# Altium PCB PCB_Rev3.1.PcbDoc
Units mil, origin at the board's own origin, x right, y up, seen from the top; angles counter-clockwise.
Board outline 1750.01 x 1055 mil, 4 copper layers (Top Layer, Layer 1 (GND), Layer 2 (PWR), Bottom Layer), stack 61.456 mil thick; 65 components, 52 nets, 278 pads, 123 vias.
Unrouted connection lines stored in the file: 3.
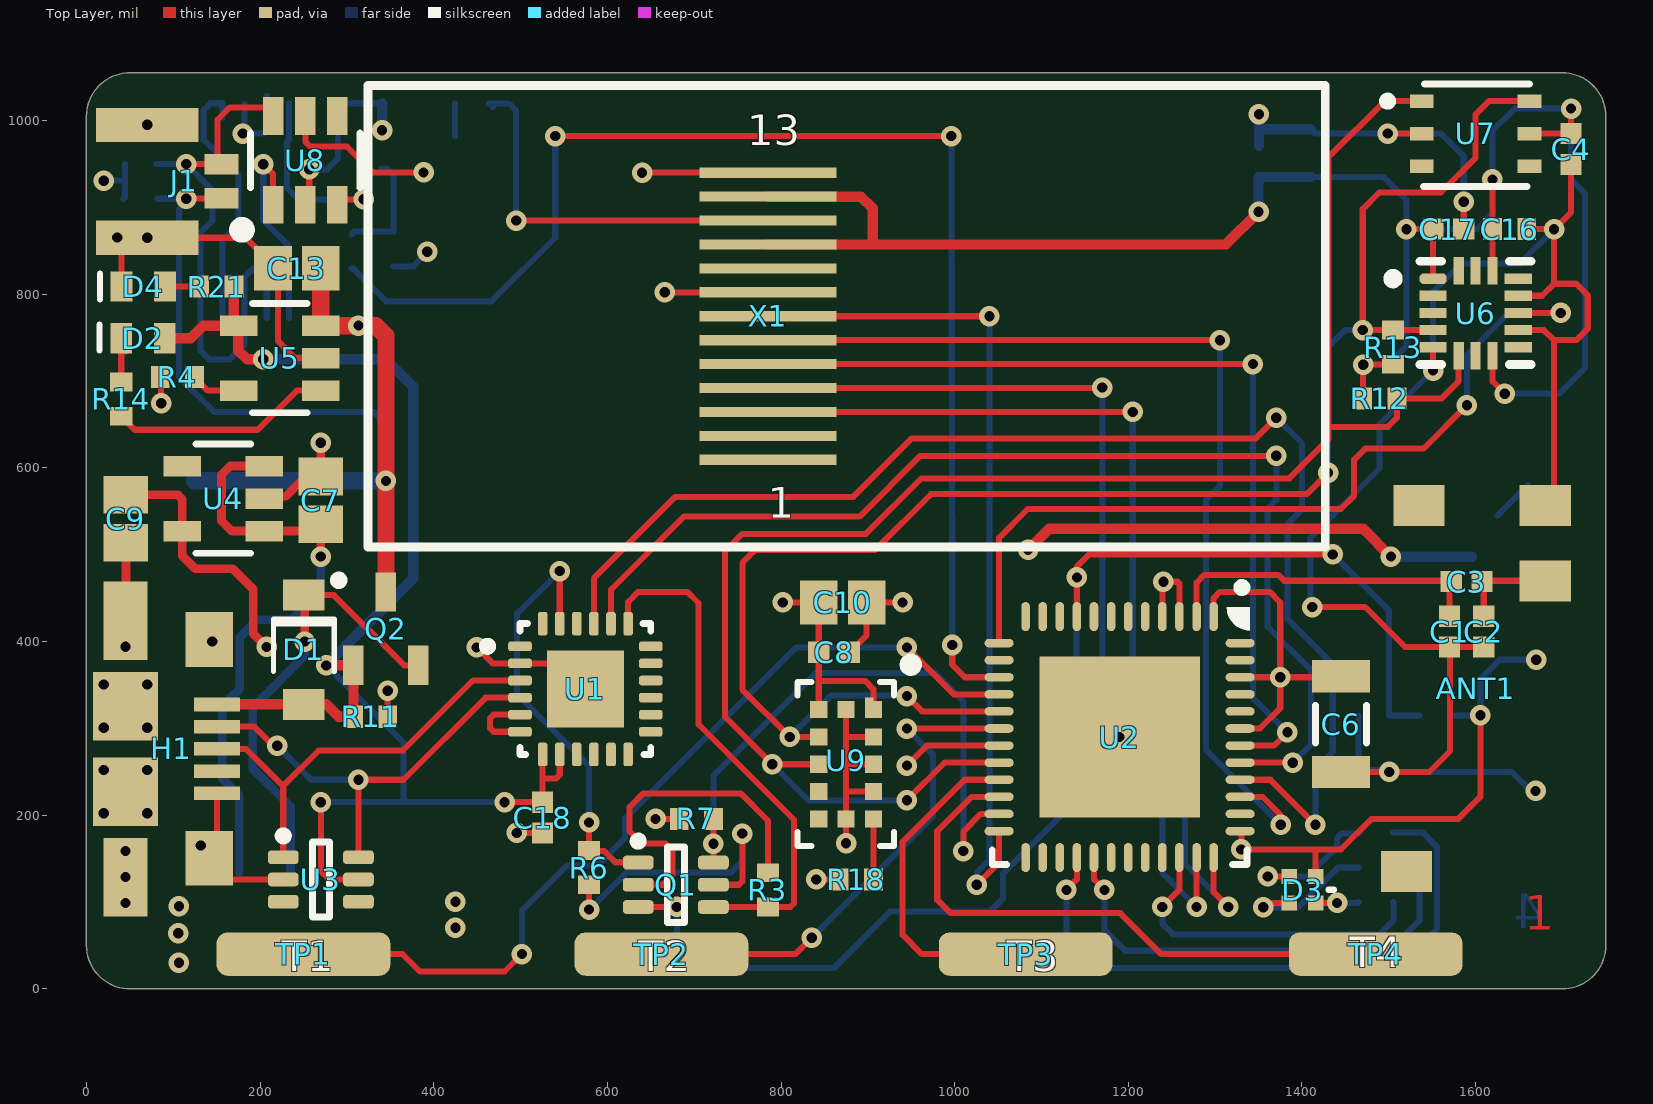
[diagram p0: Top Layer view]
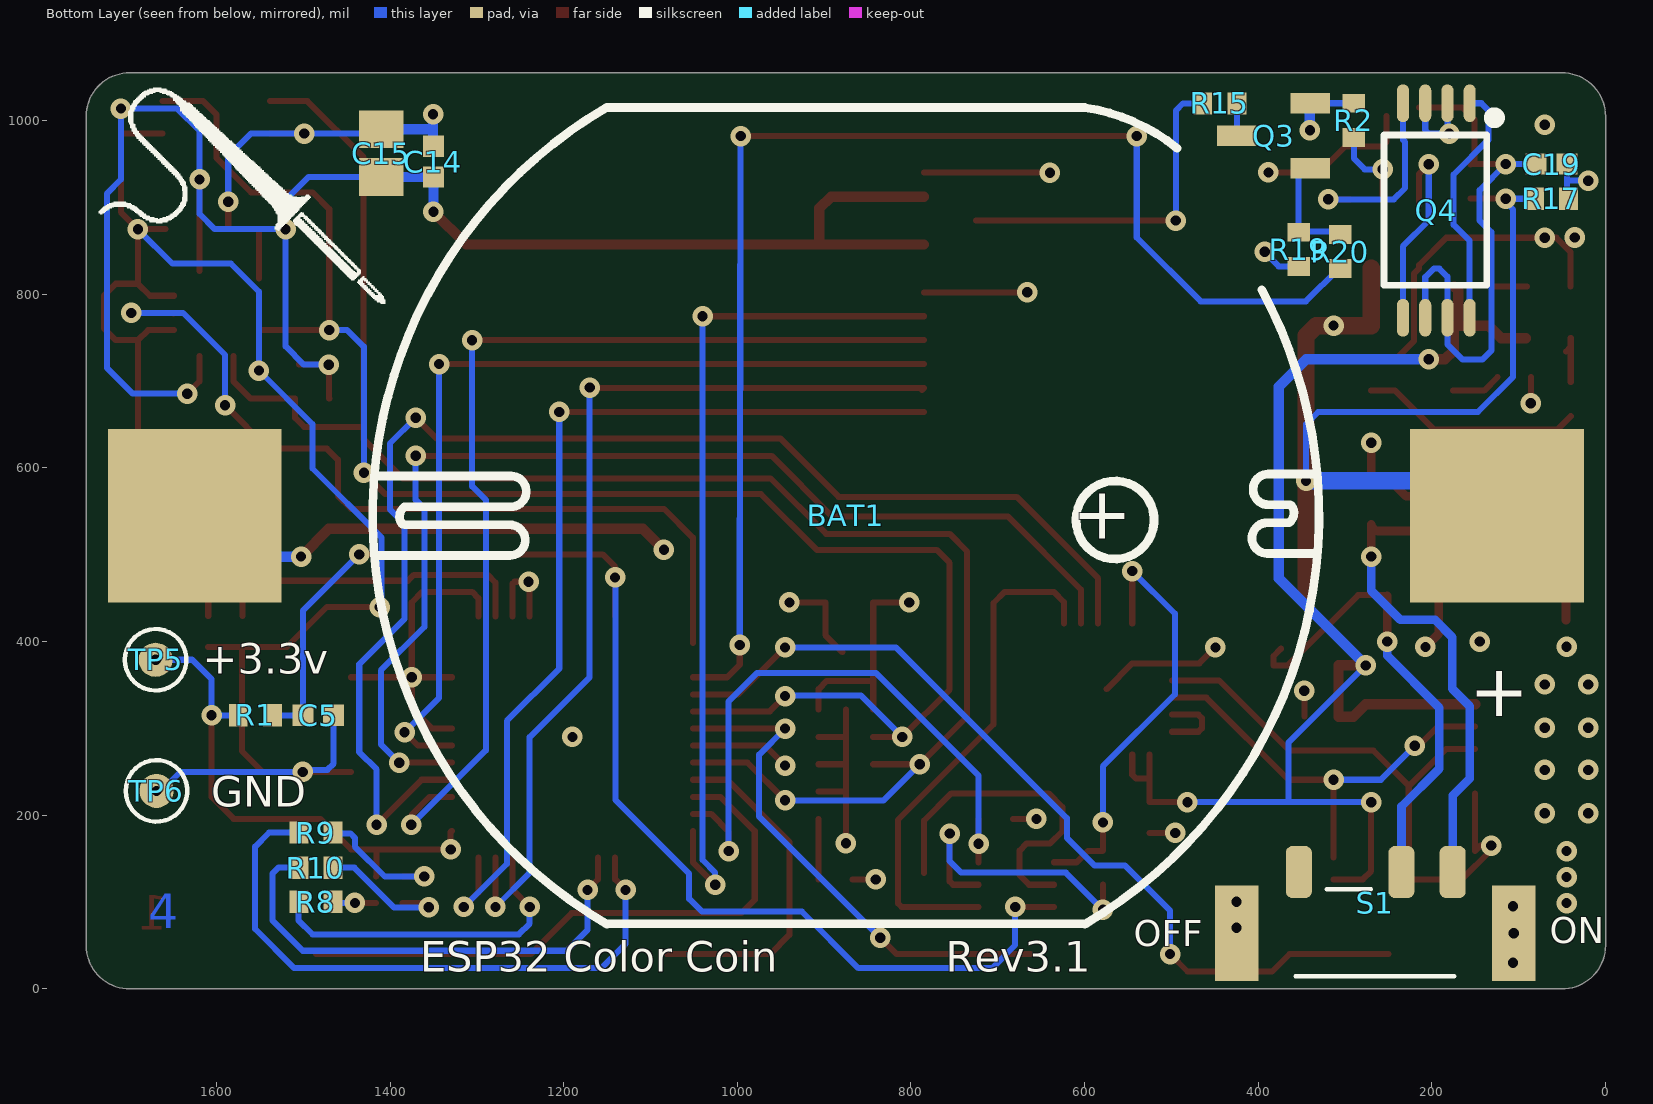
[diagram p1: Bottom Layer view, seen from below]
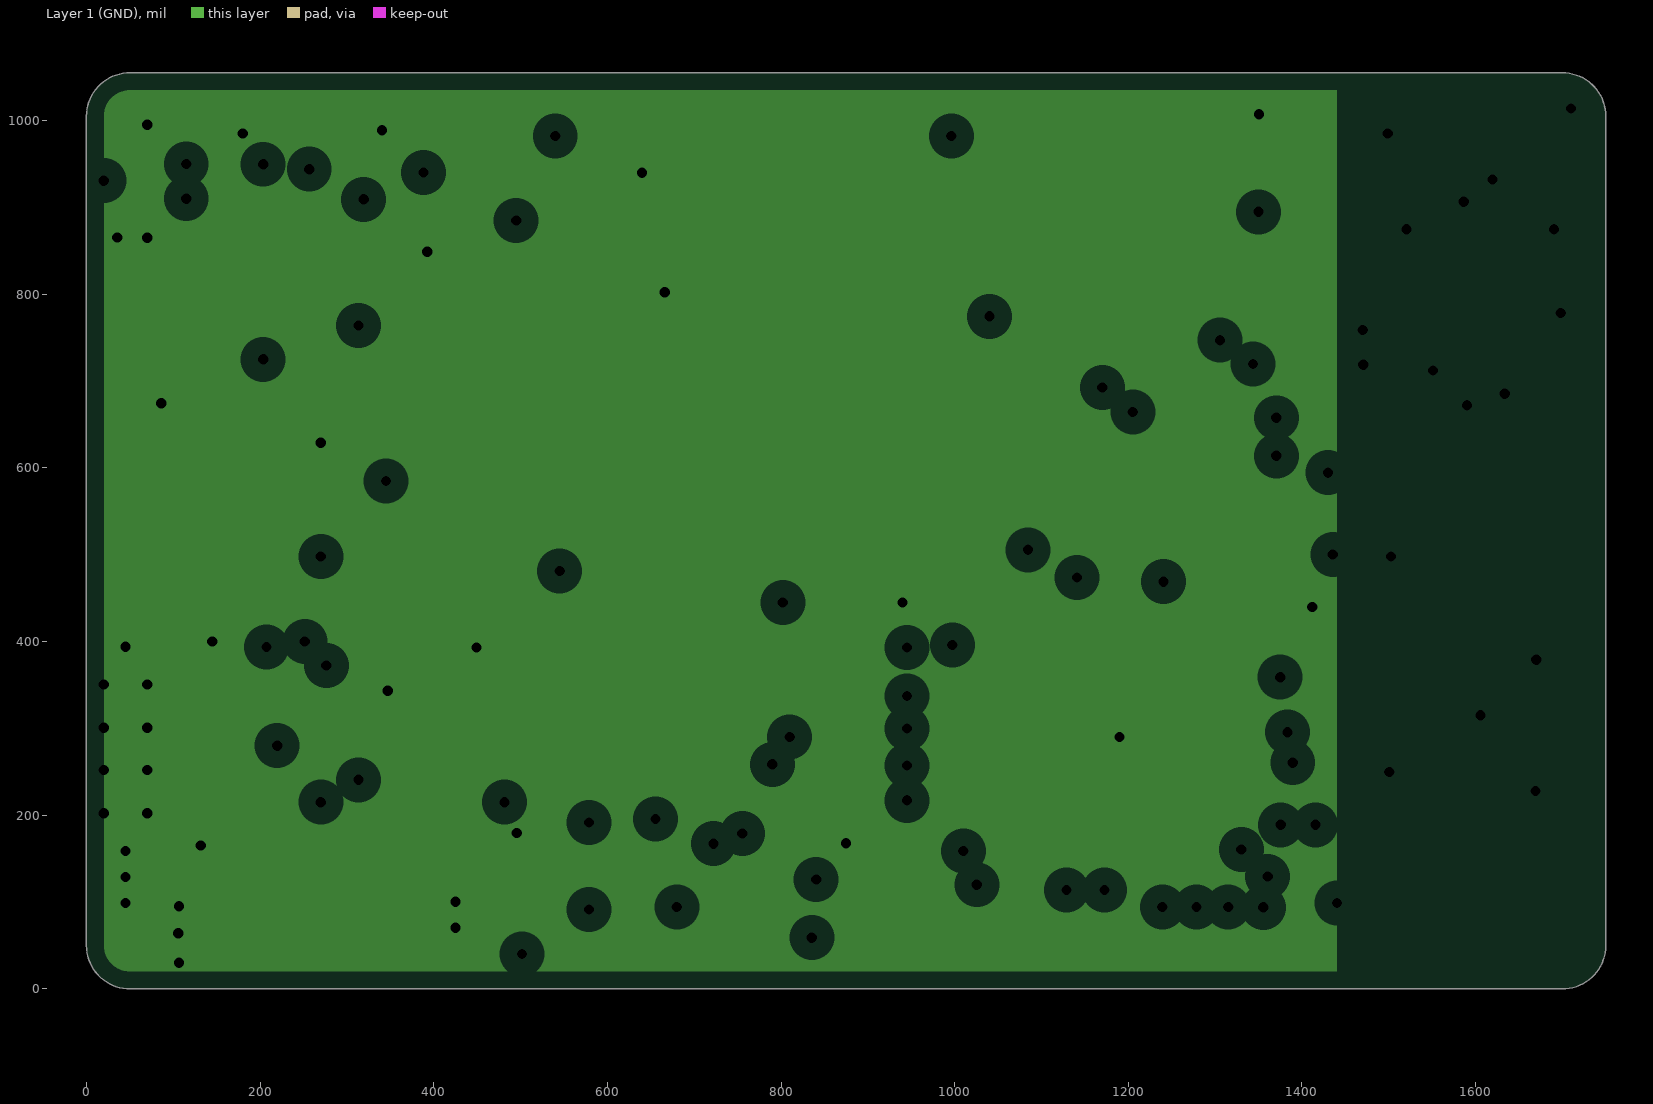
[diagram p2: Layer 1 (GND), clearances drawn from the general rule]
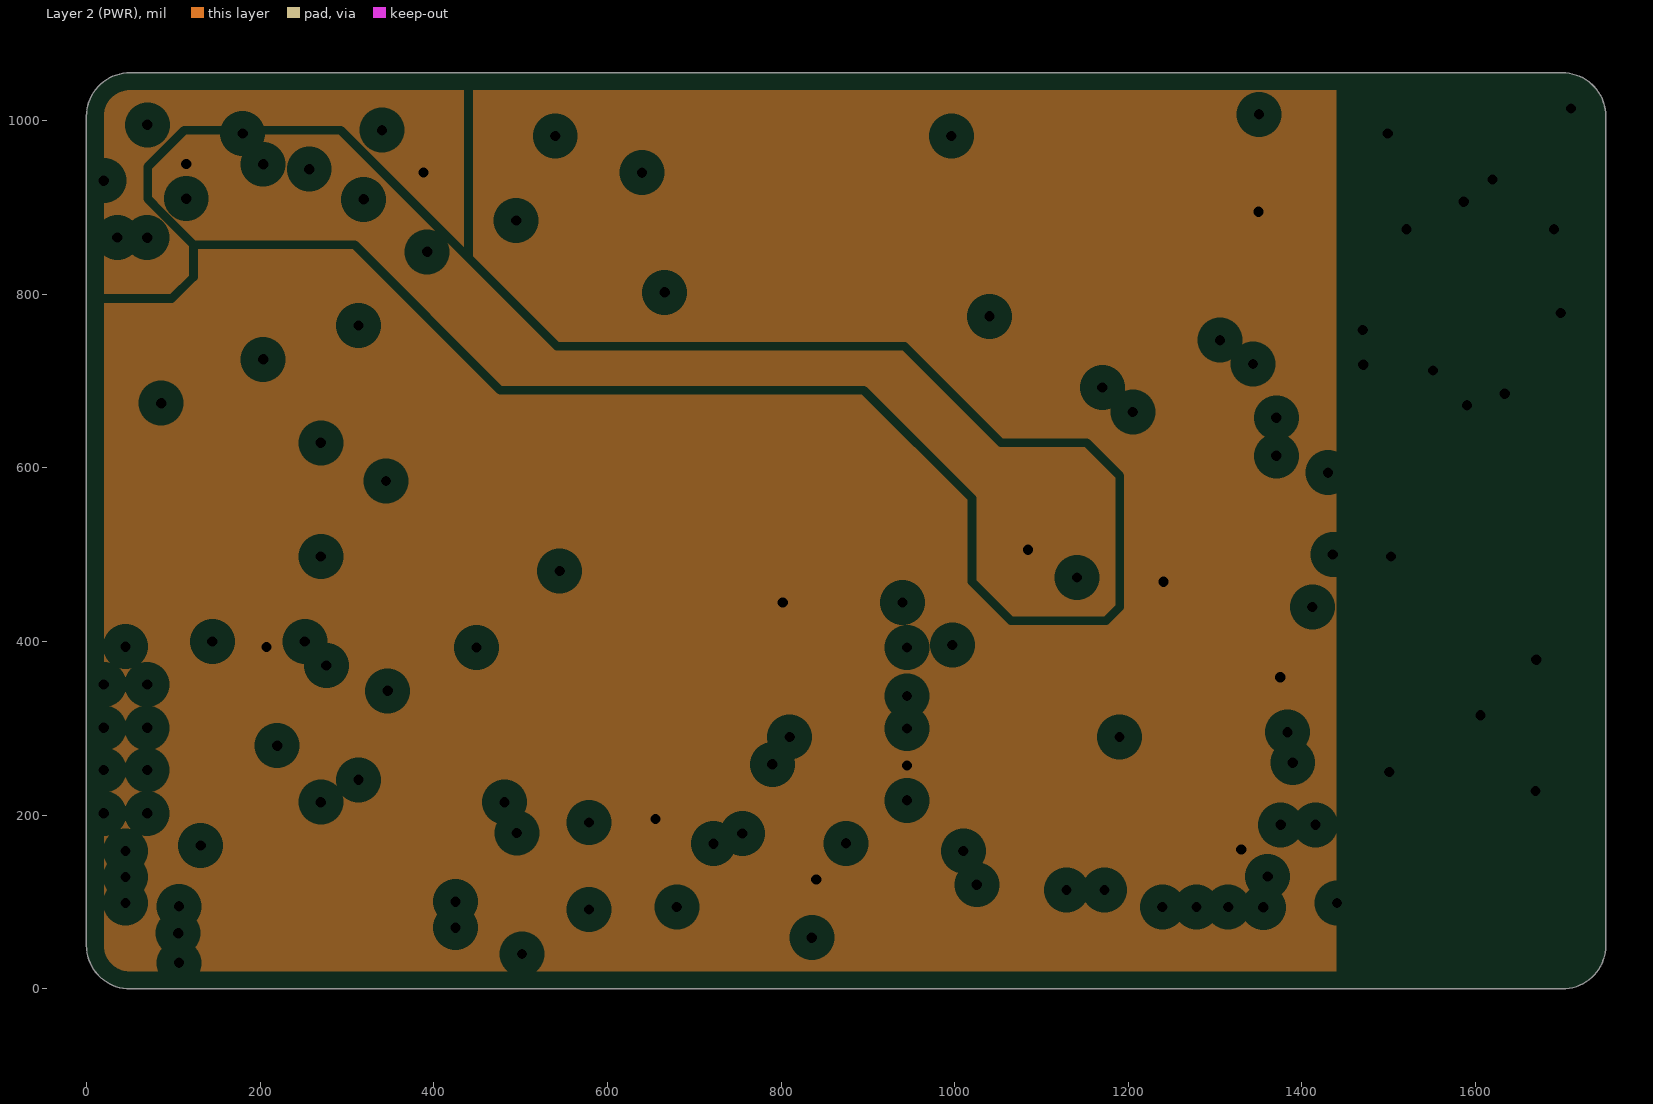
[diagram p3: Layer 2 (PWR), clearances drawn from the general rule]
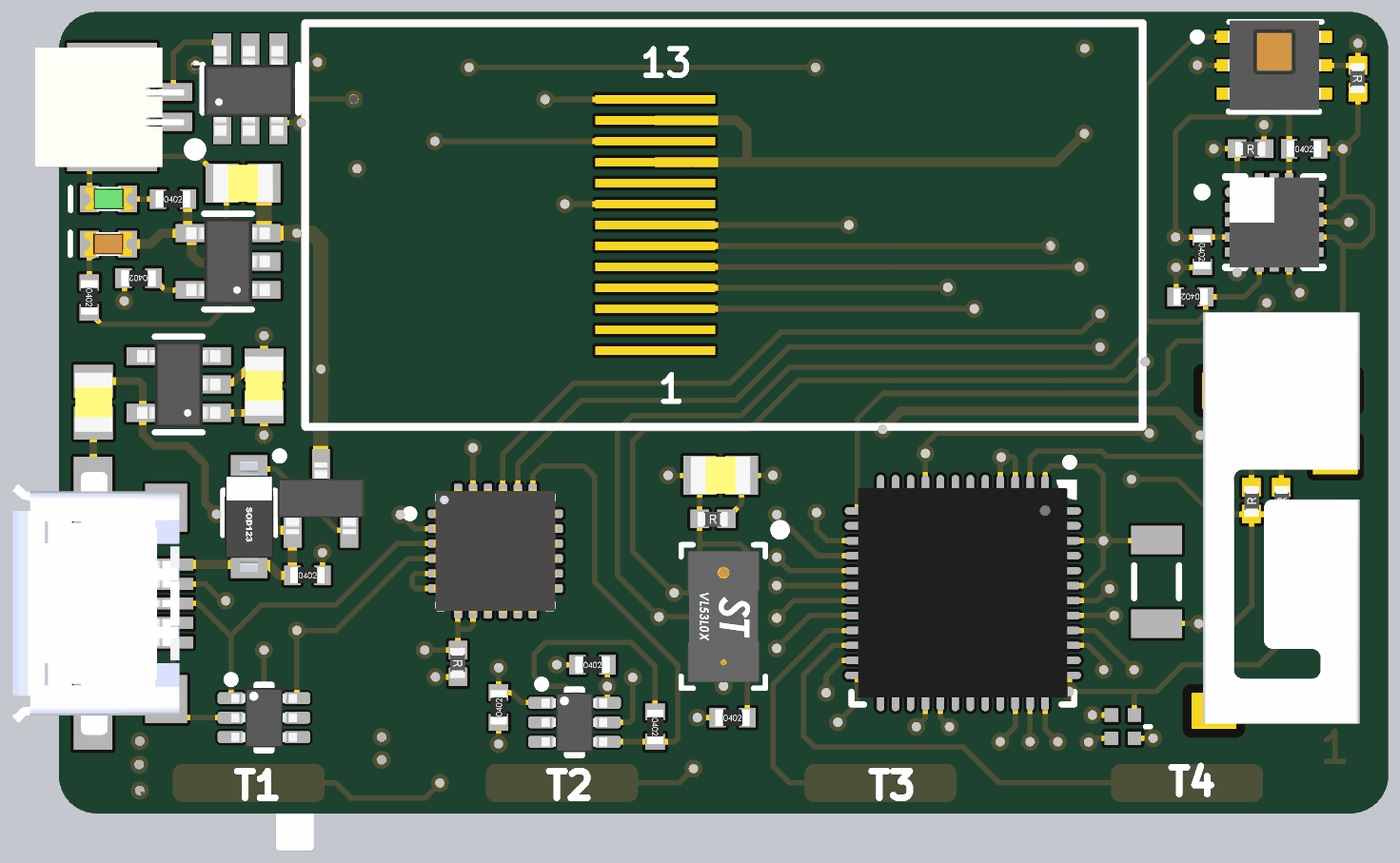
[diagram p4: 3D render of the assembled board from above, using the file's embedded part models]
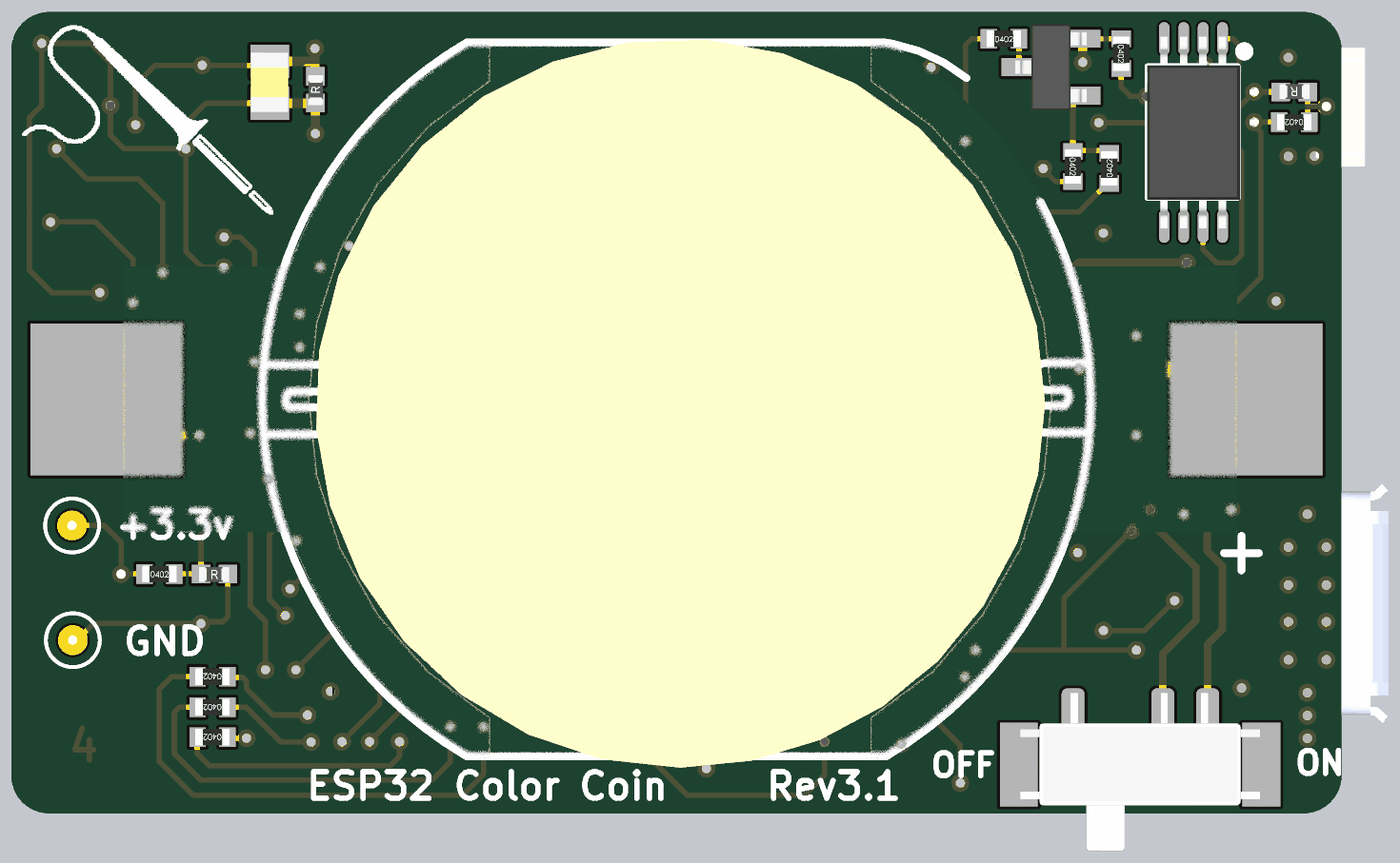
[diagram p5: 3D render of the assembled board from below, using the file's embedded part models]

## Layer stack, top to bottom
Top Solder: solder mask 0.4, Solder Resist, Dk 3.5
Top Layer: signal copper 1.4
Dielectric 2: prepreg 2.8, PP-006, Dk 4.1
Layer 1 (GND): plane copper 1.378, net GND
Dielectric 1: dielectric 50.3, FR-4, Dk 4.8
Layer 2 (PWR): plane copper 1.378, net (Multiple Nets)
Dielectric 3: prepreg 2.8, PP-006, Dk 4.1
Bottom Layer: signal copper 1.4
Bottom Solder: solder mask 0.4, Solder Resist, Dk 3.5

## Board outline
50.49,0 cw(c49.99,50) -0.01,50 -0.01,1005 cw(c49.99,1005) 50.49,1055 1699.48,1055 cw(c1699.98,1005.01) 1749.98,1005.01 1749.99,50 cw(c1699.99,50) 1699.49,0

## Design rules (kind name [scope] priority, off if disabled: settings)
Clearance Clearance_Q4 [InComponent('Q4')] p1: gap=9.2 ignorepadtopadclearanceinfootprint=FALSE
Clearance Clearance_U7 [All vs InComponent('U7')] p2: gap=7 ignorepadtopadclearanceinfootprint=FALSE
Clearance Clearance_H1 [All vs InComponent('H1')] p3: gap=9.5 ignorepadtopadclearanceinfootprint=FALSE
Clearance Clearance_U3 [All vs InComponent('U3')] p4: gap=9.5 ignorepadtopadclearanceinfootprint=FALSE
Clearance Clearance_Q1 [All vs InComponent('Q1')] p5: gap=9.5 ignorepadtopadclearanceinfootprint=FALSE
Clearance Clearance_X1 [All vs InComponent('X1')] p6: gap=8.5 ignorepadtopadclearanceinfootprint=FALSE
Clearance Clearance_U2 [All vs InComponent('U2')] p7: gap=9.5 ignorepadtopadclearanceinfootprint=FALSE
Clearance Clearance_U1 [All vs InComponent('U1')] p8: gap=7.8 ignorepadtopadclearanceinfootprint=FALSE
Clearance Clearance_U6 [All vs InComponent('U6')] p9: gap=7.5 ignorepadtopadclearanceinfootprint=FALSE
Clearance [All] p10: gap=10 ignorepadtopadclearanceinfootprint=FALSE except(0: Arc-Hole Track-Hole SMDPad-Hole THPad-Hole Via-Hole Fill-Hole Poly-Hole Region-Hole Text-Hole)
HoleSize [All] p1: absolutevalues=TRUE maxlimit=200 minlimit=1 maxpercent=80.000 minpercent=20.000
MinimumSolderMaskSliver MinimumSolderMaskSliver_U1 [All vs InComponent('U1')] p1: minsoldermaskwidth=0.5
MinimumSolderMaskSliver MinimumSolderMaskSliver_X1 [All vs InComponent('X1')] p2: minsoldermaskwidth=0.6
MinimumSolderMaskSliver [All] p3: minsoldermaskwidth=1
PlaneClearance [All] p1: clearance=20
PlaneConnect [All] p1: planeconnectstyle=Direct reliefexpansion=20 reliefentries=4 reliefconductorwidth=10 reliefairgap=10
PolygonConnect [All] p1: connectstyle=Relief reliefconductorwidth=10 reliefentries=4 polygonreliefangle="90 Angle" airgapwidth=10
RoutingVias [All] p1: holewidth=11.81 width=23.62 viastyle="Through Hole" minholewidth=11.81 minwidth=23.62 maxholewidth=11.81 maxwidth=23.62
SilkToSilkClearance [All] p1: silktosilkclearance=5
SilkToSolderMaskClearance [IsPad] p1: minsilkscreentomaskgap=5 clearancetoexposedcopper=TRUE
SolderMaskExpansion [All] p1: expansion=4 istentingtop=FALSE
Width [All] p1: maxlimit=40 minlimit=7 preferedwidth=7
24 further rules are at their usual default settings.

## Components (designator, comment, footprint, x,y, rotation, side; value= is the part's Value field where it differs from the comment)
ANT1 "RF ANT 2.4GHZ STAMPED MET SLD" PRO-OB-440 1680.36,556.61 r0 top locked
BAT1 "BATTERY-HOLDER (2450)" BU2450SM-JJ-GTR 874.99,545 r0 bottom locked value="Coin Cell Holder"
C1 "" CAPC1005X56N#1 1569.99,411.5 r90 top
C2 "" CAPC1005X56N#1 1609.36,411.5 r90 top
C3 "1.5pF" CAPC1005X56N#2 1589.71,469 r0 top
C4 "0.1uF" CAPC1005X56N#1 1709.99,967.28 r270 top
C5 "0.1uF" CAPC1005X56N#2 1482.71,315 r180 bottom
C6 "100uF" CAPC3216X160L 1444.99,304.88 r270 top
C7 "10uF" CAPC2012X140N 269.99,562.56 r90 top
C8 "0.1uF" CAPC1005X56N#2 861.21,387.76 r0 top
C9 "10uF" CAPC2012X140N 45.5,541.34 r270 top
C10 "10uF" CAPC2012X140N 871.05,445 r0 top
C13 "10uF" CAPC2012X140N 242.43,829.76 r180 top
C14 "0.1uF" CAPC1005X56N#2 1349.99,952.72 r90 bottom
C15 "10uF" CAPC2012X140N 1409.99,962.56 r90 bottom
C16 "0.1uF" RESC1005X40L 1639.13,875 r0 top
C17 "0.1uF" CAPC1005X56N#2 1568.66,875 r0 top
C18 "1uF" CAPC1005X56N#2 525.46,197.28 r270 top
C19 "0.1uF" CAPC1005X56N#2 62.27,950 r0 bottom
D1 "MBR0520" SOD123 250.5,390.56 r270 top
D2 "LED_0603" LED1608X55N-RED 65.13,749.53 r0 top value=Red
D3 "RGB" FC-B1010RGBT-HG 1400.76,114.15 r0 top value="RGB Led"
D4 "LED_0603" LED1608X55N-GREEN 65.5,808.9 r0 top locked value=Green
H1 "Micro USB" 1981584-1 97.64,276.38 r270 top
J1 "CON2" JST_Micro_2PIN 155.62,930.04 r270 top locked
Q1 "BC847S" SOT65P210X110-6N 678.81,118.9 r0 top value=2NPN
Q2 "FDN340P" SOT95P240X110-3N 344.99,414.84 r90 top value="Mosfet P-H"
Q3 "MMBT3904-TP" SOT95P240X110-3N 382.31,982.4 r0 bottom locked
Q4 "FS8205A" "TSOP65P490X110-8N WIDE" 194.95,896.48 r270 bottom locked
R1 "10K" RESC1005X40L 1555.11,315 r180 bottom
R2 "1K" RESC1005X40L 289.99,1000.32 r270 bottom
R3 "10K" RESC1005X40L 784.99,113.98 r270 top
R4 "43K" RESC1005X40L 104.81,704.53 r180 top
R6 "10K" RESC1005X40L 578.93,139.57 r90 top
R7 "10K" RESC1005X40L 702.43,195.67 r0 top
R8 "1K" RESC1005X40L 1485.31,100.21 r0 bottom
R9 "1K" RESC1005X40L 1485.31,180 r0 bottom
R10 "1K" RESC1005X40L 1485.31,139.58 r0 bottom
R11 "100K" RESC1005X40L 327.27,313.5 r0 top
R12 "2K" RESC1005X40L 1489.67,680 r180 top
R13 "2K" RESC1005X40L 1504.99,739.06 r270 top
R14 "2K" RESC1005X40L 40.13,679.21 r270 top
R15 "22R" RESC1005X40L 444.32,1019.8 r180 bottom
R17 "100R" RESC1005X40L 62.3,910 r0 bottom
R18 "10K" RESC1005X40L 886.8,125.98 r0 top
R19 "10K" RESC1005X40L 353.5,851.77 r270 bottom
R20 "1K" RESC1005X40L 305.5,849.21 r90 bottom
R21 "22K" RESC1005X40L 150.3,808.9 r0 top
S1 "SWITCH SLIDE" K3-1296S-E1 265.13,99.53 r180 bottom locked
TP1 "Test Point, 1mm Top Layer" TP100TL#1 302.05,-135 r90 top
TP2 "Test Point, 1mm Top Layer" TP100TL#2 662.27,40 r90 top
TP3 "Test Point, 1mm Top Layer" TP100TL#3 579.99,-145 r90 top
TP4 "Test Point, 1mm Top Layer" TP100TL#4 945.5,-121.1 r90 top
TP5 "Test Point, 1mm Top Layer" TP100TL#5 1669.99,379 r90 bottom
TP6 "Test Point, 1mm Top Layer" TP100TL#5 1668.99,228 r90 bottom
U1 "CP2104N" 24-QFN 574.67,345.28 r0 top
U2 "ESP32-PICO-D4" QFN48 1189.99,290 r270 top locked
U3 "PESD5V0L5UY" SOT65P210X110-6N 269.99,125 r0 top
U4 "HT7833" SOT95P280X144-5N 157.74,564.69 r180 top
U5 "SL4054ST25P" SOT95P280X144-5N 222.74,726.5 r180 top
U6 "LIS3DHTR" QFN3X3_16_1.2 1599.95,777.99 r0 top
U7 "HDC1080DMBT" HDC1080 1599.99,985 r0 top
U8 "DW01A" SOT95P280X130-6N 252.14,954.15 r90 top locked
U9 "VL53L0CXV0DH" VL53L0CXV0DH 874.99,263.09 r0 top locked value=VL53L0CXV0DH/1
X1 "TFT_0.96 inch" "TFT_GLASS 0.96 INCH" 966.09,774.65 r90 top locked

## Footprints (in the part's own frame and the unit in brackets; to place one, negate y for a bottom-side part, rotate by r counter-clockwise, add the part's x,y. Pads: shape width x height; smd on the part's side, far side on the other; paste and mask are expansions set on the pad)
24-QFN [mm] "24-QFN Exposed Pad (4x4)"
  rrect50% 0.69x0.28 smd: 1(-1.912,1.25) 2(-1.912,0.75) 3(-1.912,0.25) 4(-1.912,-0.25) 5(-1.912,-0.75) 6(-1.912,-1.25) 13(1.913,-1.25) 14(1.913,-0.75) 15(1.913,-0.25) 16(1.913,0.25) 17(1.913,0.75) 18(1.913,1.25)
  rrect50% 0.28x0.69 smd: 7(-1.25,-1.913) 8(-0.75,-1.913) 9(-0.25,-1.913) 10(0.25,-1.913) 11(0.75,-1.913) 12(1.25,-1.913) 19(1.25,1.913) 20(0.75,1.913) 21(0.25,1.913) 22(-0.25,1.913) 23(-0.75,1.913) 24(-1.25,1.913)
  rect 2.25x2.25 smd paste-1.3: 25(0,0)
  silkscreen extent -2.99,-1.91 1.91,1.91, body extent -2.05,-2.04 2.05,2.06, height 1.08
1981584-1 [mm] "CONN RCPT MICRO USB TYPE AB"
  rect 0.4x1.35 smd: 1(-1.3,1.338) 2(-0.65,1.338) 3(0,1.338) 4(0.65,1.338) 5(1.3,1.338)
  rect 2.3x1.3 smd: 6(-3.75,-1.337) 6(3.75,-1.337)
  rect 1.6x1.4 smd: 6(-3.2,1.113) 6(3.2,1.113)
  rect 2x1.9 smd: 6(-1.25,-1.337) 6(1.25,-1.337)
  body extent -4.4,-4.05 4.4,1.55, height 2.75
BU2450SM-JJ-GTR [mil] "HOLDER,BATT,COIN,24.5MM,SMT"
  rect 200x200 smd: 1(-750,0) 2(750,0)
  silkscreen extent -545,-470 545,470, body extent -842,-475 832,485, height 291
CAPC1005X56N#1 [mm] "Chip Capacitor, 2-Leads, Body 1.0x0.5mm, IPC Medium Density (0402 ceramic)"
  rect 0.62x0.62 smd paste-0.305: 1(-0.45,0) 2(0.45,0)
  body extent -0.55,-0.3 0.55,0.3, height 0.6
CAPC1005X56N#2 [mm] "Chip Capacitor, 2-Leads, Body 1.0x0.5mm, IPC Medium Density (0402 ceramic)"
  rect 0.62x0.62 smd: 1(-0.45,0) 2(0.45,0)
  body extent -0.55,-0.3 0.55,0.3, height 0.6
CAPC2012X140N [mm] "Chip Capacitor, 2-Leads, Body 2.0x1.3mm, IPC Medium Density (0805 ceramic)"
  rect 1.1x1.3 smd: 1(-0.7,0) 2(0.7,0)
  body extent -1,-0.62 1,0.63, height 1.24
CAPC3216X160L [mm] "Chip Capacitor, 2-Leads, Body 3.2x1.6mm, IPC Least Density(C1206)"
  rect 0.95x1.7 smd: 1(-1.4,0) 2(1.4,0)
  silkscreen extent -0.55,-0.75 0.55,0.75, body extent -1.7,-0.9 1.7,0.9, height 1.9
FC-B1010RGBT-HG [mm] "LED,RGB,SMD,RoHS"
  rect 0.45x0.45 smd: 1(0.387,0.388) 2(0.387,-0.387) 3(-0.387,-0.387) 4(-0.387,0.388)
  silkscreen extent 0.76,0 0.91,0, body extent -0.53,-0.55 0.53,0.58, height 0.9
HDC1080 [mm] "Temp/Humidity Sensor"
  rect 0.7x0.4 smd paste-0.381 mask+0.076: 1(-1.575,0.95) 2(-1.575,0) 3(-1.575,-0.95) 4(1.575,-0.95) 5(1.575,0) 6(1.575,0.95)
  silkscreen extent -2.7,-1.55 1.57,1.45, body extent -1.55,-1.5 1.55,1.5, height 0.85
JST_Micro_2PIN [mm]
  rect 0.6x1 smd: 1(0.5,0) 2(-0.5,0)
  rect 1x3 smd: ""(-1.65,-2.175) ""(1.65,-2.175)
  body extent -1.99,-4.74 2,0.24, height 2.9
K3-1296S-E1 [mil] "Toggle Switches SMD RoHS"
  rrect50% 30x60 smd: 1(89.06,35) 2(30,35) 3(-88.11,35)
  rect 50x110 smd: 4(-159.45,-35.43) 4(159.45,-35.43)
  silkscreen extent -92,-85 91,15, body extent -157,-149 158,59, height 60
LED1608X55N-GREEN [mil] "Chip LED GREEN 2-Leads, Body 1.6x0.8mm, IPC Medium Density (0603 med)"
  rect 25x35 smd: 1(-25,0) 2(25,0)
  body extent -31,-16 32,16, height 24
LED1608X55N-RED [mil] "Chip LED RED, 2-Leads, Body 1.6x0.8mm, IPC Medium Density (0603 med)"
  rect 25x35 smd: 1(-25,0) 2(25,0)
  body extent -31,-16 31,16, height 24
PRO-OB-440 [mm] "RF ANT 2.4GHZ STAMPED MET SLD"
  rect 1.5x1.2 smd paste-0.762 mask+0.2: 1(0,0) 2(0,-2.2)
  rect 1.5x1.2 smd paste-0.762 mask+0.3: 3(-3.7,0) 4(-4.064,-10.709)
  body extent -4.42,-11.14 0.81,2.61, height 3.56
QFN3X3_16_1.2 [mm] "QFN3X3_16_1.2"
  oct 0.8x0.3 smd: 1(-1.245,1.016)
  rect 0.8x0.3 smd: 2(-1.245,0.514) 3(-1.245,0.013) 4(-1.245,-0.489) 5(-1.245,-0.991) 9(1.245,-0.991) 10(1.245,-0.489) 11(1.245,0.013) 12(1.245,0.514) 13(1.245,1.016)
  rect 0.3x0.8 smd: 6(-0.495,-1.245) 7(0,-1.245) 8(0.495,-1.245) 14(0.495,1.245) 15(0,1.245) 16(-0.495,1.245)
  silkscreen extent -2.54,-1.5 1.63,1.52, body extent -1.51,-1.5 1.51,1.5, height 0.81
QFN48 [mm] "QFN, 48-Leads, Body 7x7mm, Pitch 0.5mm, IPC Medium Density"
  oval 0.85x0.25 smd: 1(-3.525,2.75) 2(-3.525,2.25) 3(-3.525,1.75) 4(-3.525,1.25) 5(-3.525,0.75) 6(-3.525,0.25) 7(-3.525,-0.25) 8(-3.525,-0.75) 9(-3.525,-1.25) 10(-3.525,-1.75) 11(-3.525,-2.25) 12(-3.525,-2.75) 25(3.525,-2.75) 26(3.525,-2.25) 27(3.525,-1.75) 28(3.525,-1.25) 29(3.525,-0.75) 30(3.525,-0.25) 31(3.525,0.25) 32(3.525,0.75) 33(3.525,1.25) 34(3.525,1.75) 35(3.525,2.25) 36(3.525,2.75)
  oval 0.25x0.85 smd: 13(-2.75,-3.525) 14(-2.25,-3.525) 15(-1.75,-3.525) 16(-1.25,-3.525) 17(-0.75,-3.525) 18(-0.25,-3.525) 19(0.25,-3.525) 20(0.75,-3.525) 21(1.25,-3.525) 22(1.75,-3.525) 23(2.25,-3.525) 24(2.75,-3.525) 37(2.75,3.525) 38(2.25,3.525) 39(1.75,3.525) 40(1.25,3.525) 41(0.75,3.525) 42(0.25,3.525) 43(-0.25,3.525) 44(-0.75,3.525) 45(-1.25,3.525) 46(-1.75,3.525) 47(-2.25,3.525) 48(-2.75,3.525)
  rect 4.7x4.7 smd paste-0.5: 49(0,0)
  silkscreen extent -4.5,-3.72 3.72,3.81, body extent -3.52,-3.51 3.5,3.51, height 0.78
RESC1005X40L [mm] "Chip Resistor, 2-Leads, Body 1.0x0.5mm, IPC Medium Density (0402)"
  rect 0.55x0.65 smd: 1(-0.5,0) 2(0.5,0)
  body extent -0.57,-0.27 0.58,0.28, height 0.41
SOD123 [mil] "Molded Diode, 2-Leads, Body 2.85x1.8mm, IPC Medium Density (SOD123)"
  rect 36x48 smd: 1(-63,0) 2(63,0)
  silkscreen extent -85,-35 25,45, body extent -73,-31 73,31, height 50
SOT65P210X110-6N [mm] "SC70, 6-Leads, Body 2.4x2.2mm (max), Pitch 0.65mm, IPC Medium Density"
  rrect50% 0.9x0.4 smd mask+0.076: 1(-1.1,0.675) 2(-1.1,0.025) 3(-1.1,-0.625) 4(1.1,-0.625) 5(1.1,0.025) 6(1.1,0.675)
  silkscreen extent -1.22,-1.07 0.25,1.42, body extent -1.1,-0.97 1.1,1.01, height 0.99
SOT95P240X110-3N [mm] "SOT23, 3-Leads, Body 3.0x2.5mm (max), Pitch 0.95mm, IPC Medium Density"
  rect 1.15x0.6 smd: 1(-1.075,0.95) 2(-1.075,-0.95) 3(1.075,0)
  body extent -1.2,-1.45 1.2,1.45, height 0.99
SOT95P280X130-6N [mm] "SOT23, 6-Leads, Body 3.0x3.0mm (max), Pitch 0.95mm, IPC Medium Density"
  rect 1.1x0.6 smd mask+0.051: 1(-1.3,0.94) 2(-1.3,0) 3(-1.3,-0.94) 4(1.3,-0.94) 5(1.3,0) 6(1.3,0.94)
  silkscreen extent -2.16,-1.6 0.8,1.98, body extent -1.57,-1.45 1.43,1.55, height 1.45
SOT95P280X144-5N [mm] "SOT23, 5-Leads, Body 3.1x3.0mm (max), Pitch 0.95mm, IPC Medium Density (RFMD SOT23-5)"
  rect 1.1x0.6 smd: 1(-1.2,0.95) 2(-1.2,0) 3(-1.2,-0.95) 4(1.2,-0.95) 5(1.2,0.95)
  silkscreen extent -0.8,-1.6 0.8,1.6, body extent -1.4,-1.45 1.4,1.45, height 1.45
"TFT_GLASS 0.96 INCH" [mm] "TFT_GLASS 0.96 INCH"
  rect 0.3x4 smd paste-0.305: 1(-4.2,4.6) 2(-3.5,4.6) 3(-2.8,4.6) 4(-2.1,4.6) 5(-1.4,4.6) 6(-0.7,4.6) 7(0,4.6) 8(0.7,4.6) 9(1.4,4.6) 10(2.1,4.6) 11(2.8,4.6) 12(3.5,4.6) 13(4.2,4.6)
  silkscreen extent -6.75,-11.7 6.75,16.3, body extent -6.75,-11.7 6.75,16.2, height 2
TP100TL#1 [mil] "Test Point"
  rrect50% 50x200 smd paste-80 mask-50: 1(175,52.06)
TP100TL#2 [mil] "Test Point"
  rrect50% 50x200 smd paste-80 mask+3: 1(0,0)
TP100TL#3 [mil] "Test Point"
  rrect50% 50x200 smd paste-80 mask-50: 1(185,-501.73)
TP100TL#4 [mil] "Test Point"
  rrect50% 50x200 smd paste-80 mask+3: 1(161.1,-539.49)
TP100TL#5 [mil] "Test Point"
  round 39.37 smd paste-19.68 mask+3: 1(0,0)
  silkscreen extent -35,-35 35,35
"TSOP65P490X110-8N WIDE" [mil] "TSOP, Wide, 8-Leads, Body 464x3.0mm (max), Pitch 0.65mm, IPC Medium Density"
  oval 43.5x14 smd mask+3: 1(-123.52,38.39) 2(-123.52,12.8) 3(-123.52,-12.8) 4(-123.52,-38.39) 5(123.52,-38.39) 6(123.52,-12.8) 7(123.52,12.8) 8(123.52,38.39)
  silkscreen extent -113,-60 86,73, body extent -126,-61 126,61, height 43
VL53L0CXV0DH [mm] "IC,LASER SENSOR,12pin"
  rect 0.25x0.25 smd: 1(0.675,1.713)
  rect 0.5x0.5 smd: 1(0.8,1.488) 2(0.8,0.687) 3(0.8,-0.112) 4(0.8,-0.913) 5(0.8,-1.712) 6(0,-1.712) 7(-0.8,-1.712) 8(-0.8,-0.912) 9(-0.8,-0.112) 10(-0.8,0.688) 11(-0.8,1.488) 12(0,1.488)
  silkscreen extent 1.69,2.6 2.09,3, body extent -1.2,-2.3 1.2,2.1, height 1

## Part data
ANT1: library part PRO-OB-440, Manufacturer="Proant AB"
BAT1: library part BU2450SM-JJ-GTR, "HOLDER,BATT,COIN,24.5MM,SMT", Manufacturer=MPD
C1 C2: library part CAP_0402, "DNP"
C3: library part CAP_0402, "CAP 1.5pF 0402", Manufacturer=Dafron
C4 C5 C8 C14 C16 C17 C19: library part CAP_0402, "CAP 0.1uF 0402", Manufacturer=CCTC, PartNumber=C344190
C6: library part CAP_1206, "CAP 100uF 6.3V 1206", Manufacturer="Taiyo Yuden", PartNumber=C87164
C7 C9 C10 C13 C15: library part CAP_0805, "CAP 10uF 0805", Manufacturer=Samsung, PartNumber=C307520
C18: library part CAP_0603, "CAP 1uF 16V 0402", Manufacturer=Walsin, PartNumber=C83063
D1: library part MBR0520-TP, "DIODE SCHOTTKY 20V 500MA SOD123", Manufacturer=CJ, PartNumber=C475717
D2: "LED RED CLEAR 0603 SMD", Manufacturer=FNO, PartNumber=C94869
D3: library part FC-B1010RGBT-HG, "LED,RGB LED,SMD,RoHS", Manufacturer=Foshan, PartNumber=C158099
D4: "LED Green 0603", Manufacturer=Lite-On, PartNumber=C125094
H1: library part 1981584-1, "CONN RCPT MICRO USB TYPE AB", Manufacturer="REG CON", PartNumber=C21377
J1: library part JST_Micro_CONN_2PIN, "JST MIcro CONN 2POS"
Q1: "TRANS 2NPN 44V 0.1A SC-70-6", Manufacturer=Changjiang
Q2: "MOSFET P-CH 20V 2A SOT-23", Manufacturer="On Semi", PartNumber=C75469
Q3: "TRANSISTOR NPN SOT23", Manufacturer="Micro Commercial", PartNumber=C668969
Q4: "MOSFET 2N-CH 20V 6A TSSOP-8L", Manufacturer=Fortune, PartNumber=C16052
R1 R3 R6 R7 R18 R19: library part RES_0402, "RES 10K 0402", Manufacturer=Guangdong, PartNumber=C258091
R2 R8 R9 R10 R20: library part RES_0402, "RES 1K 0402", Manufacturer=Yageo, PartNumber=C106235
R4: library part RES_0603, "RES 43K 0402", Manufacturer=Uniroyal, PartNumber=C8329
R11: library part RES_0603, "RES 100K 0402", Manufacturer="Uniroyal Elec", PartNumber=C25741
R12 R13: library part RES_0402, "RES 2K 0402", Manufacturer="LIZ Elec", PartNumber=C100291
R14: library part RES_0603, "RES 4.7K 0402", Manufacturer="LIZ Elec"
R15: library part RES_0402, "RES 22R 0402", Manufacturer=Uniroyal, PartNumber=C25092
R17: library part RES_0603, "RES 100R 0402", Manufacturer=Yageo, PartNumber=C106232
R21: library part RES_0603, "RES 22K 0402", Manufacturer="LIZ Elec"
S1: library part K3-1296S-E1, "SWITCH SLIDE SMD", Manufacturer="Korean Hroparts Elec", PartNumber=C128955
TP1 TP2 TP3 TP4 TP5 TP6: Manufacturer=N/A
U1: "IC BRIDGE USB TO UART 24QFN", Manufacturer="Silicon Labs", PartNumber=C47742
U2: "RF Transceiver ICs QFN-48_7x7x05P RoHS", Manufacturer=Espressif, PartNumber=C193707
U3: "TVS SOT-363 RoHS", Manufacturer=Yenji, PartNumber=C179747
U4: "IC LDO 3.3V 0.5A SOT23-5", Manufacturer=Holtek, PartNumber=C164106
U5: "Charger IC Lithium-Ion/Polymer SOT23-5", Manufacturer=Techfuse, PartNumber=C258510
U6: library part E-05-177, "IC ACCEL 2-16G I2C/SPI 16LGA", Manufacturer=STMicro, PartNumber=C15134
U7: "Humidity/Temperature Sensor", Manufacturer="Texas Instruments", PartNumber=C82227
U8: "IC LITHIUM BATT PROTECT SOT-23-6L", Manufacturer=PUOLOP
U9: "LASER SENSOR", Manufacturer="ST MICRO", PartNumber=C91199
X1: library part "TFT_GLASS 0.96 INCH COLOR", "0.96 INCH TFT GLASS COLOR", Manufacturer=BuyDisplay, PartNumber=ER-TFT0.96-1

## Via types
v1: diameter 23.62, hole 11.81, Top Layer to Bottom Layer, tented both sides, 123 vias

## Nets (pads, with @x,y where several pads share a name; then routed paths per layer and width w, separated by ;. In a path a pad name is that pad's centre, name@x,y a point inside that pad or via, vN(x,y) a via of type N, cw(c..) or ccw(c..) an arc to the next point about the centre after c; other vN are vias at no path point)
+3.3V: C4.1 C6.1 C8.1 C9.1 C10.1 C14.1 C15.1 C16.1 C17.1 D3.1 R1.1 R7.1 R12.2 R13.2 R18.1 TP5.1 U2.1 U2.3 U2.4 U2.19 U2.37 U2.43 U2.46 U4.5 U6.1 U6.8 U6.14 U7.5 U9.1 U9.11 X1.10 X1.12 | length 4122.7
  Top Layer w7: v1(655.5,195.67) R7.1 ; v1(802.11,445) C10.1 C8.1 843.49,354.71 ; v1(840.5,125.98) R18.1 ; U9.11 843.49,354.71 ; U9.1@906.48,321.65 906.48,345.28 897.05,354.71 843.49,354.71 ; v1(944.99,257.17) 967.98,280.16 U2.19 ; U2.4 1239.2,468.9 v1(1240.5,468.9) 1256.6,468.9 1258.89,466.61 U2.3 ; U2.1 1298.26,449.92 1305.5,457.17 1362.82,457.17 1374.99,445 v1(1374.99,358.9) ; U2.37 1328.99,181.73 1330.3,180.42 1330.13,180.25 v1(1330.13,160.53) 1415.5,160.53 ; U2.43 1351.44,299.84 1374.99,323.39 v1(1374.99,358.9) ; U2.46 v1(1374.99,358.9) ; D3.1 1415.5,129.92 1415.5,160.53 ; C6.1@1444.99,358.9 v1(1374.99,358.9) ; R12.2 1470.5,680.51 v1(1470.5,718.9) 1504.51,718.9 R13.2 ; v1(1520.36,875) C17.1 U6.1 ; v1(1605.5,315) 1605.5,221.1 1580.07,195.67 1480.13,195.67 1444.99,160.53 1415.5,160.53 ; U6.8 1619.45,699.55 v1(1633.47,685.53) ; U6.14 C16.1 v1(1619.45,932.17) ; U7.5 C4.1 v1(1709.99,1013.9)
  Top Layer w10: C9.1 105.5,568.9 110.5,563.9 U4.5 110.5,498.9 125.5,483.9 168.49,483.9 192.27,460.12 192.27,408.98 v1(207.47,393.78)
  Top Layer w12: X1.10 905.5,857.32 ; X1.12 891.96,912.44 905.5,898.9 905.5,857.32 ; v1(1349.99,895) 1312.31,857.32 905.5,857.32
  Bottom Layer w7: C15.1 1494,935 1520.36,908.64 v1(1520.36,875) ; v1(1470.5,718.9) 1499.4,718.9 1520.36,739.86 v1(1520.36,875) ; R1.1 v1(1605.5,315) 1605.5,356.63 1627.87,379 v1(1669.99,379) ; v1(1633.47,685.53) 1696.47,685.53 1726.19,715.25 1726.19,915.96 1709.99,932.17 v1(1709.99,1013.9) 1645.21,1013.9 1619.45,988.13 v1(1619.45,932.17) 1619.45,892.5 1601.95,875 v1(1520.36,875)
  Bottom Layer w12: v1(1349.99,895) C14.1 C15.1
BLUE: R9.2 U2.28 | length 713.5
  Top Layer w7: v1(1128.77,113.98) 1140.77,125.98 U2.28
  Bottom Layer w7: v1(1128.77,113.98) 1128.77,51.73 1156.6,23.9 1510.5,23.9 1555.5,68.9 1555.5,163.9 1539.4,180 R9.2
D+: H1.3 U1.3 U3.1 | length 498.5
  Top Layer w7: H1.3 183.49,276.38 226.01,233.86 ; U3.1 226.68,233.86 267.35,274.53 364.51,274.53 445.11,355.12 U1.3
D-: H1.2 U1.4 U3.6 | length 502.8
  Top Layer w7: H1.2 193.19,301.97 215.16,280 v1(219.66,280) ; U3.6 v1(313.29,240.79) 365.18,240.79 459.83,335.43 U1.4
  Bottom Layer w7: v1(219.66,280) 258.87,240.79 v1(313.29,240.79)
DC: U2.42 X1.5 | length 1059.7
  Top Layer w7: X1.5 v1(1343.5,719.53) ; U2.42 1367.78,280.16 v1(1383.22,295.59)
  Bottom Layer w7: v1(1343.5,719.53) 1343.5,335.31 v1(1383.22,295.59)
DTR: Q1.1 R6.2 U1.23 | length 499.6
  Top Layer w7: U1.23 v1(545.14,481.2) ; v1(578.93,191.69) R6.2 579.44,158.74 596.25,158.74 609.17,145.82 635.16,145.82 Q1.1
  Bottom Layer w7: v1(545.14,481.2) 495.93,431.99 495.93,339.21 578.93,256.22 v1(578.93,191.69)
EN: C5.1 Q1.3 R1.2 U2.9 | length 1518.5
  Top Layer w7: Q1.3 v1(679.99,94.29) ; U2.9 v1(1140.77,473.9) 1140.77,485.95 1155.22,500.39 v1(1435.5,500.39)
  Bottom Layer w7: v1(679.99,94.29) 679.99,50.51 706.6,23.9 860.5,23.9 925.5,88.9 1040.66,88.9 1055.5,103.74 1055.5,132.68 1140.5,217.68 1140.5,473.62 v1(1140.77,473.9) ; v1(1435.5,500.39) 1500.42,435.47 C5.1 R1.2
GND: ANT1.1 C1.1 C2.1 C4.2 C5.2 C6.2 C7.2 C8.2 C9.2 C10.2 C13.2 C14.2 C15.2 C16.2 C17.2 C18.2 D4.1 H1.5 H1.6 J1. Q3.2 Q4.2 Q4.3 R2.1 R4.2 R11.2 R19.2 S1.4 TP6.1 U1.2 U1.25 U2.49 U3.2 U4.2 U5.2 U6.5 U6.10 U6.12 U7.2 U9.2 U9.3 U9.4 U9.6 U9.12 X1.8 X1.13 | length 4242.5
  Top Layer w7: D4.1 40.5,848.89 56.68,865.08 v1(69.99,865.08) 183.49,865.08 214.87,833.7 C13.2 220.5,824.13 220.5,746.3 240.3,726.5 U5.2 ; H1.6@44.99,424.02 H1.6@45.5,424.53 ; v1(86.13,674.53) R4.2@86.13,704.53 ; H1.5 150.3,158.9 144.2,165 v1(131.56,165) 131.56,159.93 165.5,125.98 U3.2 ; U4.2 U4.2@207.47,567.17 ; C7.2@252.55,590.12 C7.2 ; R11.2 v1(346.96,343.19) ; v1(449.36,393.27) 467.83,374.8 U1.2 545.14,374.8 U1.25 ; v1(495.77,179.57) C18.2 ; v1(639.99,940) X1.13 ; v1(666.09,802.2) X1.8 ; v1(874.99,167.68) U9.6 874.99,227.17 ; U9.12 874.99,260.47 ; 876.8,290.16 U9.2 ; C8.2 898.61,407.44 C10.2 v1(939.99,445) ; U9.4 874.99,227.17 ; U9.3 876.8,258.66 874.99,260.47 ; v1(1412,439.76) 1472.66,439.76 1518.65,393.78 C1.1 ; C6.2 v1(1500.5,249.76) 1546.37,249.76 1570.5,273.9 1570.5,393.27 C1.1 ; v1(1498.77,985) U7.2 ; v1(1550.95,712.17) U6.5 ; C17.2 v1(1586.38,906.51) ; C2.1 C1.1 ; U6.10 1678.67,758.74 1690.32,747.09 ; U6.12 1676.49,798.24 1690.32,812.07 ; C16.2 v1(1690.32,875) ; ANT1.1 1690.32,566.58 1690.32,747.09 ; C4.2 1709.99,894.66 v1(1690.32,875) ; 874.99,227.17 874.99,260.47 ; 1690.32,747.09 1715.9,747.09 1729.19,760.37 1729.19,798.79 1715.9,812.07 1690.32,812.07 ; 1690.32,812.07 v1(1690.32,875)
  Top Layer w10: H1.6@45.5,424.53 C9.2 ; U4.2@207.47,567.17 229.59,567.17 C7.2@252.55,590.12 ; C7.2 v1(269.99,628.9)
  Bottom Layer w7: v1(180,985) 203.64,985 207.74,989.1 Q4.3@207.74,1028.48 ; v1@182.15,977.83 Q4.2@182.15,1019.11 ; R2.1 339.79,1020 Q3.2 Q3.2@340.5,1019.29 ; R19.2 376.5,832.08 392.5,848.08 v1(392.5,848.9) ; C14.2 C14.2@1350.5,970.94 ; 1350.5,989.05 1351.56,990.12 ; C15.2 1415.11,985 v1(1498.77,985) 1560.23,985 1586.38,958.85 v1(1586.38,906.51) ; v1(1412,439.76) 1410.01,441.75 1410.01,520.07 1489.28,599.33 1489.28,650.5 v1(1550.95,712.17) 1550.95,803 1583.19,835.25 1650.57,835.25 v1(1690.32,875) ; C5.2 1464.99,259.41 1472.23,252.17 1498.1,252.17 v1(1500.5,249.76) 1641.7,249.76 1663.47,228 v1(1668.99,228)
  Bottom Layer w12: v1(340.5,988.9) Q3.2@340.5,1019.29 ; C14.2@1350.5,970.94 1350.5,989.05 v1(1350.5,1007.17) ; 1351.56,990.12 C15.2
  other v1: 106.56,30 105.68,64.09 424.99,70.39 106.56,95 44.99,98.74 424.99,100.39 44.99,128.74 44.99,158.74 19.99,202.17 69.99,202.17 19.99,252.17 69.99,252.17 1189.99,290.16 19.99,300.59 69.99,300.59 19.99,350.59 69.99,350.59 44.99,394.02 144.99,400 35.62,865.35 70.14,995.15
GREEN: R10.2 U2.29 | length 562.8
  Top Layer w7: U2.29 1160.46,125.98 v1(1172.47,113.98)
  Bottom Layer w7: v1(1172.47,113.98) 1172.47,68.03 1196.6,43.9 1500.5,43.9 1535.5,78.9 1535.5,132.68 1528.59,139.58 R10.2
INT1: U2.13 U6.11 | length 983.4
  Top Layer w7: U2.13 1051.21,519.61 1084.5,552.9 1444.95,552.9 1460.13,568.08 1460.13,609.53 1472.77,622.17 1539.99,622.17 v1(1589.99,672.17) ; U6.11 1649.44,778 1649.93,778.49 v1(1698.19,778.49)
  Bottom Layer w7: v1(1589.99,672.17) 1589.99,730 1638.48,778.49 v1(1698.19,778.49)
IO0: Q1.6 R7.2 U2.23 | length 723.4
  Top Layer w7: Q1.6 v1(722.11,167.17) R7.2 ; v1(1009.99,158.74) 1009.99,181.18 1030.22,201.42 U2.23
  Bottom Layer w7: v1(722.11,167.17) 722.11,245.51 840.5,363.9 977.19,363.9 1009.99,331.1 v1(1009.99,158.74)
LCD_BL: R20.1 U2.15 | length 1522.1
  Top Layer w7: v1(539.99,982.17) v1(996.13,982.17) ; v1(997.27,396.02) 997.27,373.5 1011.88,358.9 U2.15
  Bottom Layer w7: R20.1 307.47,829.53 345.15,791.85 466.45,791.85 539.99,865.39 v1(539.99,982.17) ; v1(996.13,982.17) v1(997.27,396.02)
NetANT1_2: ANT1.2 C2.2 C3.2 | length 111.8
  Top Layer w7: C2.2 1609.36,470 ANT1.2
NetBAT1_2: BAT1.2 C19.2 J1.2 Q4.6 Q4.7 U8.6 | length 1236.7
  Top Layer w7: v1(114.99,950) 155.34,950 J1.2 151,954.34 151,1001 165.15,1015.15 U8.6@214.87,1015.15
  Top Layer w12: v1(1084.5,505.63) 1108.87,530 1470.4,530 v1(1502.5,497.9)
  Bottom Layer w7: C19.2 v1(114.99,950) 144.99,920 144.99,884.88 131.56,871.45 131.56,735 141.56,725 164.99,725 182.15,742.17 Q4.7 182.15,820.12 191.56,829.53 197.84,829.53 207.74,819.63 Q4.6 ; BAT1.2 BAT1.2@1660.5,580.51
  Bottom Layer w12: v1(1502.5,497.9) BAT1.2@1595.89,497.9
NetC1_2: C1.2 C3.1 U2.2 | length 377.8
  Top Layer w7: U2.2 1278.57,467.8 1287.63,476.85 1372.55,476.85 1379.4,470 1569.99,470 C1.2
NetC7_1: C7.1 S1.1 U4.1 U4.3 | length 708
  Top Layer w7: C7.1@262.27,527.28 C7.1
  Top Layer w10: U4.3 165.62,602.09 155.62,592.09 155.62,538.98 167.31,527.28 U4.1 C7.1@262.27,527.28 ; v1(269.99,497.9) C7.1
  Bottom Layer w10: S1.1 176.07,222.65 156.56,242.17 156.56,325.59 176.56,345.59 176.56,405 196.56,425 236.56,425 269.99,458.43 v1(269.99,497.9)
NetC19_1: C19.1 R17.1 U8.5 | length 245.9
  Top Layer w7: U8.5 252.14,975.71 257.7,970.15 299.9,970.15 329.74,940.32 v1(388.28,940.32)
  Bottom Layer w7: v1(19.99,930.8) 20.16,930.97 44.55,930.97 ; R17.1 44.55,911.94 44.55,930.97 ; C19.1 44.55,930.97
NetD1_1: D1.1 Q2.2 S1.2 | length 550.4
  Top Layer w7: D1.1@251.56,452.5 D1.1 285.05,453.56 366.09,372.52 Q2.2 382.39,383.35 Q2.2@374.08,391.66
  Top Layer w10: v1(251.56,400) D1.1@251.56,452.5
  Bottom Layer w10: S1.2 235.13,210 191.56,253.57 191.56,323.9 251.56,383.9 v1(251.56,400)
NetD2_1: D2.1 R14.1 | length 57.7
  Top Layer w7: R14.1 D2.1 ; D2.1@40.5,738.9 D2.1@45.5,733.9
NetD3_2: D3.2 R8.1 | length 50.2
  Top Layer w7: D3.2 v1(1440.5,98.9)
  Bottom Layer w7: v1(1440.5,98.9) 1464.31,98.9 R8.1
NetD3_3: D3.3 R10.1 | length 161.1
  Top Layer w7: v1(1355.5,93.9) 1360.5,98.9 D3.3
  Bottom Layer w7: v1(1355.5,93.9) 1395.5,93.9 1441.18,139.58 R10.1
NetD3_4: D3.4 R9.1 | length 156.9
  Top Layer w7: v1(1360.5,129.41) D3.4
  Bottom Layer w7: v1(1360.5,129.41) 1406.01,129.41 1440.5,163.9 1440.5,173.9 1445.5,178.9 1464.52,178.9 R9.1
NetD4_2: D4.2 R21.1 | length 40.1
  Top Layer w7: D4.2 R21.1
NetQ1_2: Q1.2 R3.1 | length 397.8
  Top Layer w7: Q1.2 663.88,119.88 674.99,130.98 674.99,159.25 667.07,167.17 640.07,167.17 625.5,181.73 625.5,209.24 641.46,225.2 753.46,225.2 784.99,193.67 R3.1
NetQ1_5: Q1.5 R6.1 | length 355.1
  Top Layer w7: v1(578.93,91.26) R6.1 ; Q1.5 751.48,119.88 755.5,123.9 v1(755.5,178.9) 758.77,178.9 v1@759.99,177.68
  Bottom Layer w7: v1(578.93,91.26) 621.56,133.9 742.23,133.9 755.5,147.17 v1(755.5,178.9)
NetQ3_1: Q3.1 R19.1 R20.2 | length 131.7
  Bottom Layer w7: R20.2 309.06,872.46 R19.1@353.5,872.46 ; Q3.1 345.19,945 353.5,936.69 R19.1@353.5,872.46 ; R19.1 R19.1@353.5,872.46
NetQ3_3: Q3.3 R15.2 | length 37.4
  Bottom Layer w7: Q3.3 R15.2
NetQ4_1: Q4.1 Q4.8 | length 304.2
  Bottom Layer w7: Q4.1@156,1020 143,1020 135,1012 135,977.89 174.99,937.9 174.99,880 156.6,861.61 Q4.8@156.6,772.95 ; Q4.1@156.56,1003.36 Q4.1
NetQ4_4: Q4.4 U8.3 | length 217.4
  Top Layer w7: U8.3@294.17,909.32 v1(319.28,909.32)
  Bottom Layer w7: Q4.4 233.33,977.83 230.99,975.49 230.99,922.34 244.01,909.32 v1(319.28,909.32)
NetQ4_5: Q4.5 U8.1 | length 240.6
  Top Layer w7: v1(203.64,949.72) 215.13,938.24 U8.1
  Bottom Layer w7: v1(203.64,949.72) 203.64,884.91 233.37,855.18 Q4.5
NetR2_2: R2.2 U8.2 | length 99.4
  Top Layer w7: U8.2@256.65,907.48 v1(256.65,944.05)
  Bottom Layer w7: v1@256.5,943.9 277.45,943.9 289.99,956.44 R2.2
NetR4_1: R4.1 U5.5 | length 57.4
  Top Layer w7: R4.1 139.93,689.09 U5.5
NetR14_2: R14.2 U5.1 | length 255.1
  Top Layer w7: R14.2 55.76,643.9 197.27,643.9 242.47,689.09 U5.1
NetR15_1: R15.1 X1.11 | length 396.7
  Top Layer w7: v1(494.99,884.88) X1.11@724.99,884.88
  Bottom Layer w7: R15.1@468.03,1015.77 R15.1 486.7,1019.8 494.99,1011.51 v1(494.99,884.88)
NetU1_5: U1.5 U1.6 | length 83.7
  Top Layer w7: U1.6 469.09,296.06 464.99,300.16 464.99,311.65 469.09,315.75 U1.5
RED: R8.2 U2.34 | length 385.7
  Top Layer w7: v1(1239.2,94.29) 1258.89,113.98 U2.34
  Bottom Layer w7: v1@1240.5,92.99 v1(1239.2,94.29) 1239.2,75.2 1251.72,62.68 1489.28,62.68 1505.5,78.9 1505.5,99.7 R8.2
RST: U2.39 X1.6 | length 1187.5
  Top Layer w7: X1.6 v1(1305.5,747.09) ; U2.39 1354.55,221.1 1375.5,200.16 v1(1375.5,188.9)
  Bottom Layer w7: v1(1305.5,747.09) 1305.5,578.9 1289.68,563.08 1289.68,274.72 v1(1375.5,188.9)
RTS: Q1.4 R3.2 U1.19 | length 602.3
  Top Layer w7: U1.19 623.88,445.55 635.5,457.17 692.19,457.17 704.99,444.37 704.99,304.67 814.99,194.67 814.99,98.39 810.89,94.29 R3.2 Q1.4
RXD: U1.21 U2.40 | length 1541.1
  Top Layer w7: U1.21 584.51,472.8 678.3,566.58 883.18,566.58 950.5,633.9 1346.64,633.9 v1(1370.5,657.76) ; U2.40 1363.61,240.79 v1(1415.5,188.9)
  Bottom Layer w7: v1(1370.5,657.76) 1400.13,628.13 1400.13,552.18 1383.19,535.25 1383.19,426.19 1435.5,373.88 1435.5,272.68 1415.5,252.68 v1(1415.5,188.9)
SCL: R13.1 U2.17 U6.4 U7.6 U9.10 | length 1928.8
  Top Layer w7: U9.10 v1(809.99,290.16) 755.5,344.65 755.5,490.63 770.5,505.63 908.45,505.63 972.72,569.9 1405.5,569.9 v1(1430.13,594.53) ; v1(944.99,337.17) 962.63,319.53 U2.17 ; U6.4 R13.1 v1(1469.99,758.74) 1469.99,898.08 1489.07,917.17 1559.99,917.17 1599.99,957.17 1599.99,1007.17 1615.22,1022.4 U7.6
  Bottom Layer w7: v1(809.99,290.16) 857.82,337.99 944.16,337.99 v1(944.99,337.17) ; v1(1430.13,594.53) 1430.13,739.53 1449.34,758.74 v1(1469.99,758.74)
SDA: R12.1 U2.20 U6.6 U7.1 U9.9 | length 2039.3
  Top Layer w7: U9.9 v1(789.99,258.66) 735.5,313.15 735.5,503.9 755.5,523.9 897.78,523.9 961.78,587.9 1385.5,587.9 1430.5,632.9 1430.5,647.17 ; v1(944.99,217.17) 988.29,260.47 U2.20 ; U7.1 1495.22,1022.4 1430.5,957.68 1430.5,647.17 ; U6.6 1580.45,699.55 1560.89,680 R12.1 1509.36,657.76 1498.77,647.17 1430.5,647.17
  Bottom Layer w7: v1(789.99,258.66) 831.48,217.17 v1(944.99,217.17)
SPI_CLK: U2.35 X1.4 | length 1088.7
  Top Layer w7: X1.4@787.43,689.53 X1.4 v1@1170.13,691.97 ; v1(1278.57,94.29) U2.35
  Bottom Layer w7: v1(1170.13,692.53) 1170.13,358.9 1239.2,289.83 1239.2,133.66 v1(1278.57,94.29)
SPI_MOSI: U2.36 X1.3 | length 1099.6
  Top Layer w7: X1.3 v1(1205.13,664.41) ; U2.36 1298.26,111.02 v1(1314.99,94.29)
  Bottom Layer w7: v1(1205.13,664.41) 1205.13,368.9 1265.5,308.53 1265.5,143.78 v1(1314.99,94.29)
TFT_CS: U2.24 X1.7 | length 988.6
  Top Layer w7: X1.7 v1(1039.99,774.65) ; v1(1025.5,119.88) 1051.21,145.59 U2.24
  Bottom Layer w7: v1(1025.5,119.88) 1025.5,133.9 1039.99,148.39 v1(1039.99,774.65) v1@1039.99,775
TOUCH_1: TP1.1 U2.16 | length 1029
  Top Layer w7: TP1.1 364.08,40 384.08,20 481.56,20 v1(501.56,40) ; v1(944.99,393.27) 999.04,339.21 U2.16
  Bottom Layer w7: v1(501.56,40) 501.56,90 553.73,142.17 588.77,142.17 620.5,173.9 620.5,196.46 817.3,393.27 v1(944.99,393.27)
TOUCH_2: TP2.1 U2.18 | length 601.7
  Top Layer w7: TP2.1 816.6,40 v1(835.5,58.9) ; v1(944.99,299.84) U2.18
  Bottom Layer w7: v1(835.5,58.9) 974.99,198.39 974.99,269.84 v1(944.99,299.84) v1@942.66,302.17
TOUCH_3: TP3.1 U2.21 | length 398.8
  Top Layer w7: U2.21 1011.56,240.79 939.99,169.21 939.99,62.17 962.15,40 TP3.1
TOUCH_4: TP4.1 U2.22 | length 697.5
  Top Layer w7: U2.22 1019.44,221.1 979.99,181.65 979.99,102.6 995.42,87.17 1190.88,87.17 1238.04,40 TP4.1
TXD: U1.20 U2.41 | length 1317
  Top Layer w7: U1.20 604.2,459.86 688.24,543.9 890.5,543.9 960.5,613.9 v1(1370.5,613.9) ; U2.41 v1(1389.4,260.47)
  Bottom Layer w7: v1(1370.5,613.9) 1370.5,563.08 1360.5,553.08 1360.5,416.73 1410.5,366.73 1410.5,281.57 v1(1389.4,260.47)
VBAT: BAT1.1 C13.1 J1.1 Q2.3 R17.2 U5.3 | length 1269.9
  Top Layer w7: v1@114.99,910.39 J1.1@155.58,910.39
  Top Layer w20: C13.1 U5.3 v1(313.29,763.9) 333.26,763.9 344.99,752.17 v1(344.99,585) Q2.3
  Bottom Layer w7: R17.2 v1(114.99,910) 114.99,906.01 106.56,897.59 106.56,705 147.15,664.41 331.09,664.41 344.99,650.51 v1(344.99,585)
  Bottom Layer w20: BAT1.1@124.48,585 v1(344.99,585)
VUSB: C18.1 D1.2 D2.2 H1.1 Q2.1 R11.1 R21.2 U1.7 U1.8 U3.5 U5.4 | length 1684
  Top Layer w7: U5.4@169.81,772.21 168.5,770.9 U5.4 ; R21.2@169.81,804.35 169.81,808.72 R21.2 ; v1(269.99,215) 269.99,135.63 279.63,125.98 U3.5 ; v1(481.56,215) C18.1 525.46,242.49 ; U1.7 525.46,242.49 ; U1.8 545.14,246.59 541.04,242.49 525.46,242.49
  Top Layer w12: D2.2@92.13,749.53 120.13,749.53 134.5,763.9 U5.4 174.99,763.39 174.99,735 184.99,725 v1(203.64,725) ; H1.1 D1.2 276.37,327.56 290.42,313.5 R11.1 Q2.1 v1(276.37,372.52) ; U5.4@169.81,772.21 169.81,804.35 R21.2@174.36,808.9
  Bottom Layer w7: v1(269.99,215) 364.99,215 ; v1(276.37,372.52) 364.99,283.9 364.99,215 ; v1(481.56,215) 364.99,215
  Bottom Layer w12: v1(203.64,725) 344.99,725 376.5,693.49 376.5,472.65 v1(276.37,372.52)
XSHUT: R18.2 U9.5 | length 69.7
  Top Layer w7: R18.2 U9.5
pads on no net: ANT1.3 ANT1.4 H1.4 S1.3 U1.1 U1.9 U1.10 U1.11 U1.12 U1.13 U1.14 U1.15 U1.16 U1.17 U1.18 U1.22 U1.24 U2.5 U2.6 U2.7 U2.8 U2.10 U2.11 U2.12 U2.14 U2.25 U2.26 U2.27 U2.30 U2.31 U2.32 U2.33 U2.38 U2.44 U2.45 U2.47 U2.48 U3.3 U3.4 U4.4 U6.2 U6.3 U6.7 U6.9 U6.13 U6.15 U6.16 U7.3 U7.4 U8.4 U9.7 U9.8 X1.1 X1.2 X1.9

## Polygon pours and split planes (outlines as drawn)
GND on Layer 1 (GND) (split plane): 50.49,1034.9 50.54,1034.9 1440.5,1034.9 1440.5,20.1 50.49,20.1 49.75,20.02 45.3,20.37 40.72,21.47 36.37,23.27 32.36,25.73 28.78,28.79 25.72,32.37 23.26,36.38 21.46,40.73 20.36,45.31 20.03,49.49 20.08,50 20.08,1005 20.03,1005.5 20.36,1009.69 21.46,1014.27 23.26,1018.61 25.72,1022.63 28.78,1026.21 32.36,1029.26 36.37,1031.72 40.72,1033.52 45.3,1034.62 49.75,1034.97
+3.3V on Layer 2 (PWR) (split plane): 1440,1034.9 1440,20.1 50.49,20.1 49.75,20.02 45.3,20.37 40.72,21.47 36.37,23.27 32.36,25.73 28.78,28.79 25.72,32.37 23.26,36.38 21.46,40.73 20.36,45.31 20.03,49.49 20.08,50 20.08,789.9 98.41,789.9 100.36,790.29 102.02,791.4 126.95,816.32 128.05,817.98 128.44,819.93 128.44,851.9 306.88,851.9 472.85,685.92 474.51,684.82 476.46,684.43 893.35,684.43 1014.89,562.89 1014.89,468.9 1015.28,466.95 1016.38,465.29 1061.26,420.41 1062.92,419.31 1064.87,418.92 1174.24,418.92 1176.19,419.31 1177.84,420.41 1193.59,436.16 1194.7,437.81 1195.09,439.76 1195.09,590.92 1194.7,592.87 1193.59,594.53 1155.62,632.5 1153.96,633.61 1152.01,634 1055.37,634 945.76,743.6 944.1,744.71 942.15,745.1 544.1,745.1 444.94,844.26 445.09,845 445.09,1034.9
NetBAT1_2 on Layer 2 (PWR) (split plane): 538.38,736.4 540.04,735.29 541.99,734.9 940.04,734.9 1049.65,625.29 1051.3,624.19 1053.26,623.8 1149.9,623.8 1184.89,588.81 1184.89,441.88 1172.13,429.11 1066.98,429.11 1025.09,471.01 1025.09,565 1024.7,566.95 1023.59,568.6 899.06,693.13 897.41,694.24 895.46,694.63 478.57,694.63 312.59,860.6 310.94,861.71 308.99,862.1 125.45,862.1 89.1,898.45 75.6,911.95 75.6,944.58 114.82,983.8 290.98,983.8
NetC19_1 on Layer 2 (PWR) (split plane): 50.49,1034.9 50.54,1034.9 434.89,1034.9 434.89,854.31 296.69,992.5 295.04,993.61 293.09,994 112.71,994 110.76,993.61 109.1,992.5 66.89,950.29 65.79,948.64 65.4,946.69 65.4,909.84 65.79,907.89 66.89,906.24 81.89,891.24 118.24,854.89 118.24,822.04 96.3,800.1 20.08,800.1 20.08,1005 20.03,1005.5 20.36,1009.69 21.46,1014.27 23.26,1018.61 25.72,1022.63 28.78,1026.21 32.36,1029.26 36.37,1031.72 40.72,1033.52 45.3,1034.62 49.75,1034.97

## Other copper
Top Layer:
  text "1" at 1656.19,68.06 h40
Bottom Layer:
  text "4" at 1678.49,70 h40
Layer 1 (GND) (plane layer: these items are gaps in the copper):
  pour cut-out: 1441,1055 1440.5,1054.5 1440.5,0 1749.99,0 1749.98,0.02 1749.98,1055 1440.5,1055
  text "2" at 1650.87,68.06 h40
Layer 2 (PWR) (plane layer: these items are gaps in the copper):
  pour cut-out: 1440.49,1065 1440,1064.5 1440,10 1749.49,10 1749.48,10.01 1749.48,1065 1440,1065
  lines w10: -0.01,795 98.41,795 123.34,819.93 123.34,857 ; 439.99,845 439.99,1055 ; 1538.5,448.9 1547.5,457.9 ; 123.34,857 85.5,894.84 70.5,909.84 70.5,946.69 112.71,988.9 293.09,988.9 541.99,740 942.15,740 1053.26,628.9 1152.01,628.9 1189.99,590.92 1189.99,439.76 1174.24,424.02 1064.87,424.02 1019.99,468.9 1019.99,565 895.46,689.53 476.46,689.53 308.99,857 123.34,857
  text "3" at 1650.55,66.22 h40

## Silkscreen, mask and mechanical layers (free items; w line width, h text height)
Top Overlay:
  lines w7: 14.99,735 14.99,765 ; 15.5,793.9 15.5,823.9 ; 819.18,180.48 819.18,164.67 834.99,164.67 ; 819.18,337.83 819.18,353.64 834.99,353.64 ; 914.29,164.67 930.11,164.67 930.11,180.48 ; 914.29,353.64 930.11,353.64 930.11,337.83
  text "T4" at 1454.99,25 h35
  text "T1" at 224.99,20 h35
  text "T2" at 635.7,20 h35
  text "T3" at 1060.07,20 h35
Bottom Overlay:
  drawing of 541 lines, arcs and shapes, not listed
  text "+3.3v" at 1615.99,363 h35
  text "GND" at 1605.99,210 h35
  text "Rev3.1" at 760.13,19.53 h35
  text "ESP32 Color Coin" at 1365.13,19.53 h35
Mechanical 1:
  the board outline again, w10
Top_Assembly:
  lines w2: 1429.63,88.37 1429.63,140 1375,140 1375,88 1430,88 ; 832,183.67 832,333 918,333 918,183.67 832,183.67
Bottom_Assembly:
  lines w2: 148,807 148,988.9 242,988.9 242,807 148,807

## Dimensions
50.49,1055 to 50.49,0 on Drill Drawing
-0.01,1005 to 1749.98,1005.01 on Drill Drawing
